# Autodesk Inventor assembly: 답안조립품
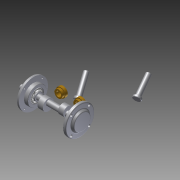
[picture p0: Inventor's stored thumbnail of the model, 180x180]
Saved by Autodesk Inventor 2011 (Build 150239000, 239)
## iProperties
Created: 2014-12
Part Number: 답안조립품
Document SubType Name: Assembly
Designer: user
Author: user
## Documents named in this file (9)
- D:\441225V1009\답안조립품.iam
- D:\441225V1009\2.본체.ipt
- D:\441225V1009\앞커버.ipt
- D:\441225V1009\뒷커버.ipt
- D:\441225V1009\3. 축.ipt
- D:\441225V1009\베어링 6203.ipt
- D:\441225V1009\오일실.ipt
- D:\441225V1009\부시.ipt
- D:\441225V1009\슬라이더.ipt
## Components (5 placed, 4 different names)
1. 2.본체:1
2. 3. 축:1
3. 7-베어링 6203:1
4. 8-오일실:1
5. 7-베어링 6203:2
